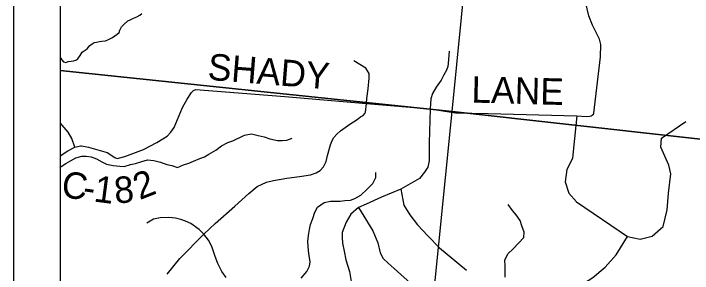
# Model space of a CAD drawing. Extents: x 0 to 34, y 0 to 22.
# Drawn here: x 2 to 3.46, y 19.466 to 20.024 of the extents above; entities that cross this region are included whole.
import ezdxf

# ---------------------------------------------------------------- set-up
doc = ezdxf.new("R2010")
doc.units = 0
for name, color, linetype in [('GM_X_Corporation', 7, 'Continuous'), ('GM_X_County_Road', 7, 'Continuous'), ('GM_X_County_Road_Text', 7, 'Continuous'), ('GM_X_Minor_River', 7, 'Continuous'), ('GM_X_Township_Road', 7, 'Continuous'), ('SH_Data', 7, 'Continuous')]:
    doc.layers.add(name, color=color, linetype=linetype)

msp = doc.modelspace()

# ---------------------------------------------------------------- linework, layer by layer
at = {"layer": 'GM_X_Corporation'}
for points in [[(8.9, 20.9), (2.1, 20.9), (2.1, 18.7697), (2.2164, 18.6603), (2.3024, 18.5638), (2.4531, 18.3722), (2.5091, 18.2757), (2.5944, 18.157), (2.6477, 18.0827), (2.8129, 17.7895), (2.9482, 17.5994), (3.2529, 17.1208), (3.3535, 16.9293), (3.4766, 16.7367)], [(4.0645, 20.9), (2.1, 20.9), (2.1, 18.7697)]]:
    msp.add_lwpolyline(points, dxfattribs=at)
for points in [[(2.1, 20.8994), (2.1, 19.9022), (2.9428, 19.8144), (3.042, 20.8099)], [(4.0476, 20.7082), (3.9403, 19.7031), (2.9428, 19.8144), (3.042, 20.8099)], [(2.1, 19.9022), (2.1, 18.897), (2.8429, 18.8167), (2.9428, 19.8144)], [(2.9428, 19.8144), (3.9403, 19.7031), (3.8378, 18.696), (2.8429, 18.8167)]]:
    msp.add_lwpolyline(points, close=True, dxfattribs=at)
at = {"layer": 'GM_X_County_Road'}
msp.add_lwpolyline([(2.1, 19.719), (2.1164, 19.7298), (2.1318, 19.7373), (2.1412, 19.7399), (2.1438, 19.7403), (2.1452, 19.7404), (2.1461, 19.7403), (2.1614, 19.7373), (2.2013, 19.726), (2.2178, 19.7153), (2.2225, 19.7135), (2.2253, 19.7136), (2.2395, 19.7178), (2.2793, 19.7327), (2.3078, 19.7479), (2.3302, 19.761), (2.3384, 19.7695), (2.3455, 19.7799), (2.363, 19.8224), (2.3734, 19.8404), (2.3829, 19.8546), (2.3872, 19.859), (2.3922, 19.8611), (2.5831, 19.8466), (2.759, 19.8312), (2.8955, 19.8202), (2.9503, 19.8115), (3.0205, 19.81), (3.2114, 19.8047), (3.2321, 19.8036), (3.239, 19.8038), (3.2419, 19.8048), (3.244, 19.806), (3.2466, 19.8085), (3.2479, 19.8108), (3.2621, 19.9317), (3.2624, 19.9577), (3.2602, 19.9694), (3.245, 19.9995), (3.237, 20.0194), (3.2307, 20.0466)], dxfattribs=at)
at = {"layer": 'GM_X_Minor_River'}
for points in [[(2.1, 19.9303), (2.1029, 19.9258), (2.1073, 19.9207), (2.1125, 19.9197), (2.1175, 19.9215), (2.1236, 19.9224), (2.129, 19.923), (2.1336, 19.9247), (2.1383, 19.9276), (2.1431, 19.9346), (2.1478, 19.9413), (2.158, 19.949), (2.1643, 19.9556), (2.169, 19.9592), (2.1736, 19.9621), (2.1786, 19.9634), (2.1847, 19.9644), (2.19, 19.9649), (2.1977, 19.9662), (2.2038, 19.969), (2.2127, 19.9733), (2.2174, 19.9765), (2.2225, 19.9802), (2.2271, 19.9838), (2.2288, 19.9887), (2.2317, 19.9962), (2.2372, 20.0013), (2.2455, 20.0086), (2.2508, 20.0107), (2.2582, 20.0143), (2.2648, 20.0178), (2.2713, 20.0207), (2.276, 20.0247)], [(2.1, 19.6935), (2.1025, 19.6957), (2.1126, 19.7022), (2.1223, 19.708), (2.1338, 19.7145), (2.1465, 19.718), (2.1563, 19.7181), (2.1669, 19.7166), (2.1786, 19.7125), (2.1898, 19.7061), (2.1995, 19.7013), (2.2143, 19.6985), (2.2283, 19.6966), (2.2377, 19.696), (2.2515, 19.7001), (2.2622, 19.7025), (2.276, 19.707), (2.2883, 19.7105), (2.3019, 19.7086), (2.3159, 19.7055), (2.3298, 19.7006), (2.3404, 19.698), (2.3528, 19.6942), (2.3655, 19.6996), (2.3766, 19.7034), (2.3866, 19.7073), (2.4008, 19.7134), (2.4104, 19.7169), (2.4201, 19.7227), (2.4347, 19.7314), (2.4468, 19.7406), (2.461, 19.7474), (2.4718, 19.7509), (2.4968, 19.7635), (2.5117, 19.7661), (2.526, 19.7623), (2.5385, 19.7596), (2.5509, 19.7555), (2.5675, 19.7516), (2.5774, 19.7517), (2.5873, 19.7525), (2.5992, 19.7567)], [(2.6186, 19.4562), (2.6308, 19.4703), (2.6364, 19.4819), (2.6375, 19.4914), (2.6356, 19.5052), (2.634, 19.5147), (2.6331, 19.5258), (2.633, 19.5353), (2.6338, 19.5482), (2.6364, 19.561), (2.6386, 19.5712), (2.6432, 19.5844), (2.6481, 19.5983), (2.6538, 19.6088), (2.6677, 19.6187), (2.6811, 19.6213), (2.6917, 19.6218), (2.702, 19.6219), (2.7123, 19.6227), (2.7241, 19.6239), (2.7341, 19.6274), (2.7464, 19.6347), (2.7605, 19.6476), (2.7722, 19.6598), (2.7787, 19.6725), (2.779, 19.6828)], [(3.0573, 19.4581), (3.0572, 19.468), (3.0572, 19.4817), (3.0565, 19.495), (3.0626, 19.5086), (3.0743, 19.5192), (3.0856, 19.5315), (3.0974, 19.5433), (3.0977, 19.5551), (3.0932, 19.5685), (3.0893, 19.5804), (3.0809, 19.5921), (3.0729, 19.6018), (3.0637, 19.6146)]]:
    msp.add_lwpolyline(points, dxfattribs=at)
at = {"layer": 'GM_X_Township_Road'}
for points in [[(2.9369, 19.9434), (2.9342, 19.9172), (2.9336, 19.9105), (2.9311, 19.903), (2.9244, 19.8912), (2.9192, 19.8818), (2.9085, 19.8663), (2.9009, 19.853), (2.8974, 19.8414), (2.8955, 19.8202), (2.8935, 19.747), (2.8939, 19.7209), (2.8936, 19.7079), (2.8904, 19.6943), (2.8838, 19.6842), (2.8726, 19.6702), (2.8324, 19.6476), (2.7911, 19.6302), (2.7578, 19.6153), (2.7413, 19.608), (2.725, 19.5934), (2.715, 19.5764), (2.7067, 19.5545), (2.7065, 19.5433), (2.707, 19.5316), (2.7107, 19.5144), (2.7145, 19.4954), (2.722, 19.4703), (2.7257, 19.4492)], [(2.3305, 19.4646), (2.3572, 19.4985), (2.4091, 19.5507), (2.4333, 19.5736), (2.4757, 19.6105), (2.5058, 19.6384), (2.5236, 19.6532), (2.5441, 19.6625), (2.5586, 19.6661), (2.5877, 19.6711), (2.6149, 19.6747), (2.6384, 19.678), (2.6509, 19.6823), (2.659, 19.6877), (2.6667, 19.6953), (2.6723, 19.7066), (2.6747, 19.7193), (2.6814, 19.7429), (2.6851, 19.7517), (2.6888, 19.7581), (2.6948, 19.7654), (2.7027, 19.7725), (2.7227, 19.7866), (2.7387, 19.7971), (2.7461, 19.8024), (2.7515, 19.8059), (2.7555, 19.8098), (2.7567, 19.8127), (2.759, 19.8312), (2.7598, 19.8423), (2.7625, 19.8629), (2.7646, 19.8856), (2.7643, 19.896), (2.7573, 19.9072), (2.7318, 19.9229)], [(3.2114, 19.8047), (3.2038, 19.7357), (3.2018, 19.7129), (3.1894, 19.6894), (3.1859, 19.6632), (3.1942, 19.639), (3.2101, 19.6204), (3.3198, 19.5458)], [(3.3198, 19.5458), (3.3474, 19.5403), (3.373, 19.5465), (3.3965, 19.5672), (3.4054, 19.6031), (3.4082, 19.639), (3.413, 19.6805), (3.4089, 19.6991), (3.3916, 19.7378), (3.393, 19.7571), (3.4455, 19.793)], [(2.1318, 19.7373), (2.1251, 19.7561), (2.1175, 19.7699), (2.1091, 19.7797), (2.1008, 19.7888), (2.1, 19.7898)], [(2.8324, 19.6476), (2.8394, 19.613), (2.8521, 19.5925), (2.8682, 19.5704), (2.8904, 19.5471), (2.9159, 19.5217), (2.9738, 19.4734)], [(2.7413, 19.608), (2.7724, 19.5576), (2.7834, 19.532), (2.7883, 19.5106), (2.7945, 19.4982), (2.8055, 19.4885), (2.8186, 19.4768), (2.9104, 19.3947), (2.9305, 19.3802), (2.9422, 19.356), (2.9484, 19.327), (2.9526, 19.3063), (2.9491, 19.2842), (2.9367, 19.258), (2.9381, 19.2331)], [(2.4573, 19.4574), (2.4475, 19.4707), (2.4389, 19.4878), (2.4335, 19.5027), (2.4261, 19.5245), (2.419, 19.5376), (2.4091, 19.5507), (2.3994, 19.5606), (2.3812, 19.5734), (2.3697, 19.5786), (2.3597, 19.5822), (2.348, 19.5854), (2.334, 19.5865), (2.3153, 19.586), (2.3011, 19.5827), (2.2866, 19.5746)], [(3.1942, 19.4236), (3.2253, 19.4451), (3.2453, 19.4575), (3.2722, 19.4796), (3.2957, 19.5065), (3.3198, 19.5458)]]:
    msp.add_lwpolyline(points, dxfattribs=at)
at = {"layer": 'SH_Data'}
for p, q in [((2, 21), (2, 14)), ((2.1, 20.9), (2.1, 14.1))]:
    msp.add_line(p, q, dxfattribs=at)

# ---------------------------------------------------------------- texts
at = {"layer": 'GM_X_County_Road_Text'}
for s, height, rotation, p in [('SHADY', 0.05682, 355.4176, (2.4161, 19.8825)), ('LANE', 0.05682, 358.4524, (2.984, 19.8334)), ('C', 0.0568, 352.1264, (2.1008, 19.6308)), ('2', 0.0568, 21.7261, (2.2712, 19.6235)), ('1', 0.0568, 352.5704, (2.1706, 19.6211)), ('8', 0.0568, 4.8806, (2.2186, 19.6163)), ('-', 0.0568, 352.205, (2.1471, 19.6243))]:
    msp.add_text(s, height=height, rotation=rotation, dxfattribs=at).set_placement(p)

doc.saveas('drawing.dxf')
